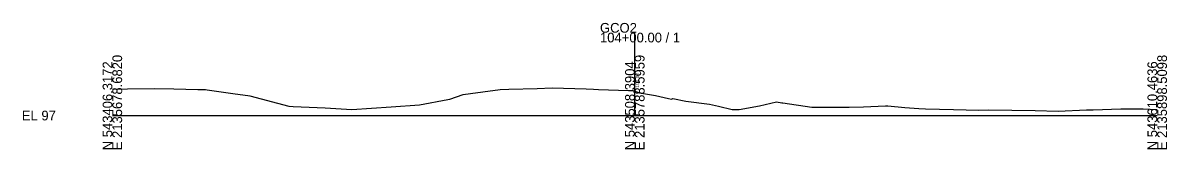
# Model space of a CAD drawing. Extents: x -14327 to 8886, y -10 to 39048.
# Drawn here: x 3974.3 to 4302.8, y 27990.3 to 28026.7 of the extents above; entities that cross this region are included whole.
import ezdxf

# ---------------------------------------------------------------- set-up
doc = ezdxf.new("R2010")
doc.units = 0
for name, color, linetype in [('RD_GPK_XS_Cell', 7, 'Continuous'), ('RD_XS_ExGround', 7, 'Continuous'), ('RD_XS_TX_Elev_EX', 7, 'Continuous')]:
    doc.layers.add(name, color=color, linetype=linetype)

msp = doc.modelspace()

# ---------------------------------------------------------------- linework, layer by layer
at = {"layer": 'RD_GPK_XS_Cell'}
for p, q in [((4150, 28000), (4150, 28023.86)), ((4000, 28000), (4150, 28000)), ((4150, 28000), (4300, 28000))]:
    msp.add_line(p, q, dxfattribs=at)
at = {"layer": 'RD_XS_ExGround'}
for p, q in [((4000, 28007.56), (4000.19, 28007.57)), ((4000.19, 28007.57), (4004.33, 28007.66)), ((4004.33, 28007.66), (4012.08, 28007.82)), ((4012.08, 28007.82), (4017.62, 28007.67)), ((4017.62, 28007.67), (4024.53, 28007.49)), ((4024.53, 28007.49), (4026.73, 28007.45)), ((4026.73, 28007.45), (4027.19, 28007.43)), ((4027.19, 28007.43), (4035.26, 28006.28)), ((4108.5, 28007.14), (4110.71, 28007.42)), ((4110.71, 28007.42), (4111.31, 28007.52)), ((4111.31, 28007.52), (4113.84, 28007.59)), ((4113.84, 28007.59), (4121.96, 28007.83)), ((4121.96, 28007.83), (4126.29, 28007.95)), ((4126.29, 28007.95), (4136.07, 28007.67)), ((4136.07, 28007.67), (4138.17, 28007.61)), ((4138.17, 28007.61), (4139.61, 28007.54)), ((4139.61, 28007.54), (4148.22, 28007.2)), ((4035.26, 28006.28), (4038.85, 28005.78)), ((4038.85, 28005.78), (4039.49, 28005.63)), ((4039.49, 28005.63), (4050.66, 28002.71)), ((4088.16, 28003.08), (4096.31, 28004.65)), ((4096.31, 28004.65), (4096.88, 28004.76)), ((4096.88, 28004.76), (4100.69, 28006.07)), ((4100.69, 28006.07), (4108.5, 28007.14)), ((4148.22, 28007.2), (4149.41, 28007.21)), ((4149.41, 28007.21), (4150, 28007.02)), ((4150, 28007.02), (4151.37, 28006.57)), ((4151.37, 28006.57), (4155.95, 28005.74)), ((4155.95, 28005.74), (4159.7, 28004.89)), ((4159.7, 28004.89), (4160.52, 28004.72)), ((4160.52, 28004.72), (4160.9, 28004.9)), ((4160.9, 28004.9), (4164.63, 28004.17)), ((4164.63, 28004.17), (4171.44, 28003.26)), ((4050.66, 28002.71), (4051.95, 28002.64)), ((4051.95, 28002.64), (4061.07, 28002.21)), ((4061.07, 28002.21), (4068.74, 28001.76)), ((4068.74, 28001.76), (4080.01, 28002.49)), ((4080.01, 28002.49), (4088.16, 28003.08)), ((4171.44, 28003.26), (4174, 28002.67)), ((4174, 28002.67), (4177.92, 28001.77)), ((4177.92, 28001.77), (4179.96, 28001.74)), ((4179.96, 28001.74), (4185.82, 28002.79)), ((4185.82, 28002.79), (4190.68, 28003.9)), ((4190.68, 28003.9), (4192.17, 28003.68)), ((4192.17, 28003.68), (4192.52, 28003.63)), ((4192.52, 28003.63), (4200.83, 28002.38)), ((4200.83, 28002.38), (4201.13, 28002.38)), ((4201.13, 28002.38), (4210.74, 28002.44)), ((4210.74, 28002.44), (4211.53, 28002.38)), ((4211.53, 28002.38), (4215.7, 28002.55)), ((4215.7, 28002.55), (4222, 28002.82)), ((4222, 28002.82), (4222.65, 28002.82)), ((4222.65, 28002.82), (4227.58, 28002.35)), ((4227.58, 28002.35), (4231.54, 28001.99)), ((4231.54, 28001.99), (4233.49, 28001.93)), ((4233.49, 28001.93), (4241.55, 28001.71)), ((4241.55, 28001.71), (4248.8, 28001.58)), ((4248.8, 28001.58), (4251.56, 28001.64)), ((4251.56, 28001.64), (4264.96, 28001.42)), ((4264.96, 28001.42), (4271.57, 28001.29)), ((4271.57, 28001.29), (4279.68, 28001.63)), ((4279.68, 28001.63), (4281.58, 28001.61)), ((4281.58, 28001.61), (4289.54, 28001.97)), ((4289.54, 28001.97), (4295.98, 28001.9)), ((4295.98, 28001.9), (4300, 28001.69))]:
    msp.add_line(p, q, dxfattribs=at)

# ---------------------------------------------------------------- texts
at = {"layer": 'RD_GPK_XS_Cell'}
for s, p in [('GCO2', (4140, 28023.86)), ('104+00.00 / 1', (4140, 28021.06)), ('EL 97', (3974, 27998.6))]:
    msp.add_text(s, height=2.8, dxfattribs=at).set_placement(p)
for s, p in [('E 2135678.6820', (4002.8, 27990)), ('E 2135788.5959', (4152.8, 27990)), ('E 2135898.5098', (4302.8, 27990)), ('N 543406.3172', (4000, 27990)), ('N 543508.3904', (4150, 27990)), ('N 543610.4636', (4300, 27990))]:
    msp.add_text(s, height=2.8, rotation=90, dxfattribs=at).set_placement(p)
at = {"layer": 'RD_XS_TX_Elev_EX'}
msp.add_text('104.02', height=1, rotation=90, dxfattribs=at).set_placement((4151.25, 28008.02))

doc.saveas('drawing.dxf')
